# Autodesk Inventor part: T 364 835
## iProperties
Created: 2005-12
Part Number: T 364 835
Material: 1.0110.01
Description: Gewindeplatte
Vendor: Autodesk Inc.
Document SubType Name: Modeling
Standard: DIN 1017
Designer: I.Baliuc
Size Designation: 20 x 8 - 80
Density: 7.84 g/cm^3
Zweck: für Stromschienenbefestigung
Author: T.Messerschmitt
Keywords: 266558
Revision Number: 364835
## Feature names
1. Körper [Extrusion]
2. Bohrung1 [Hole]
